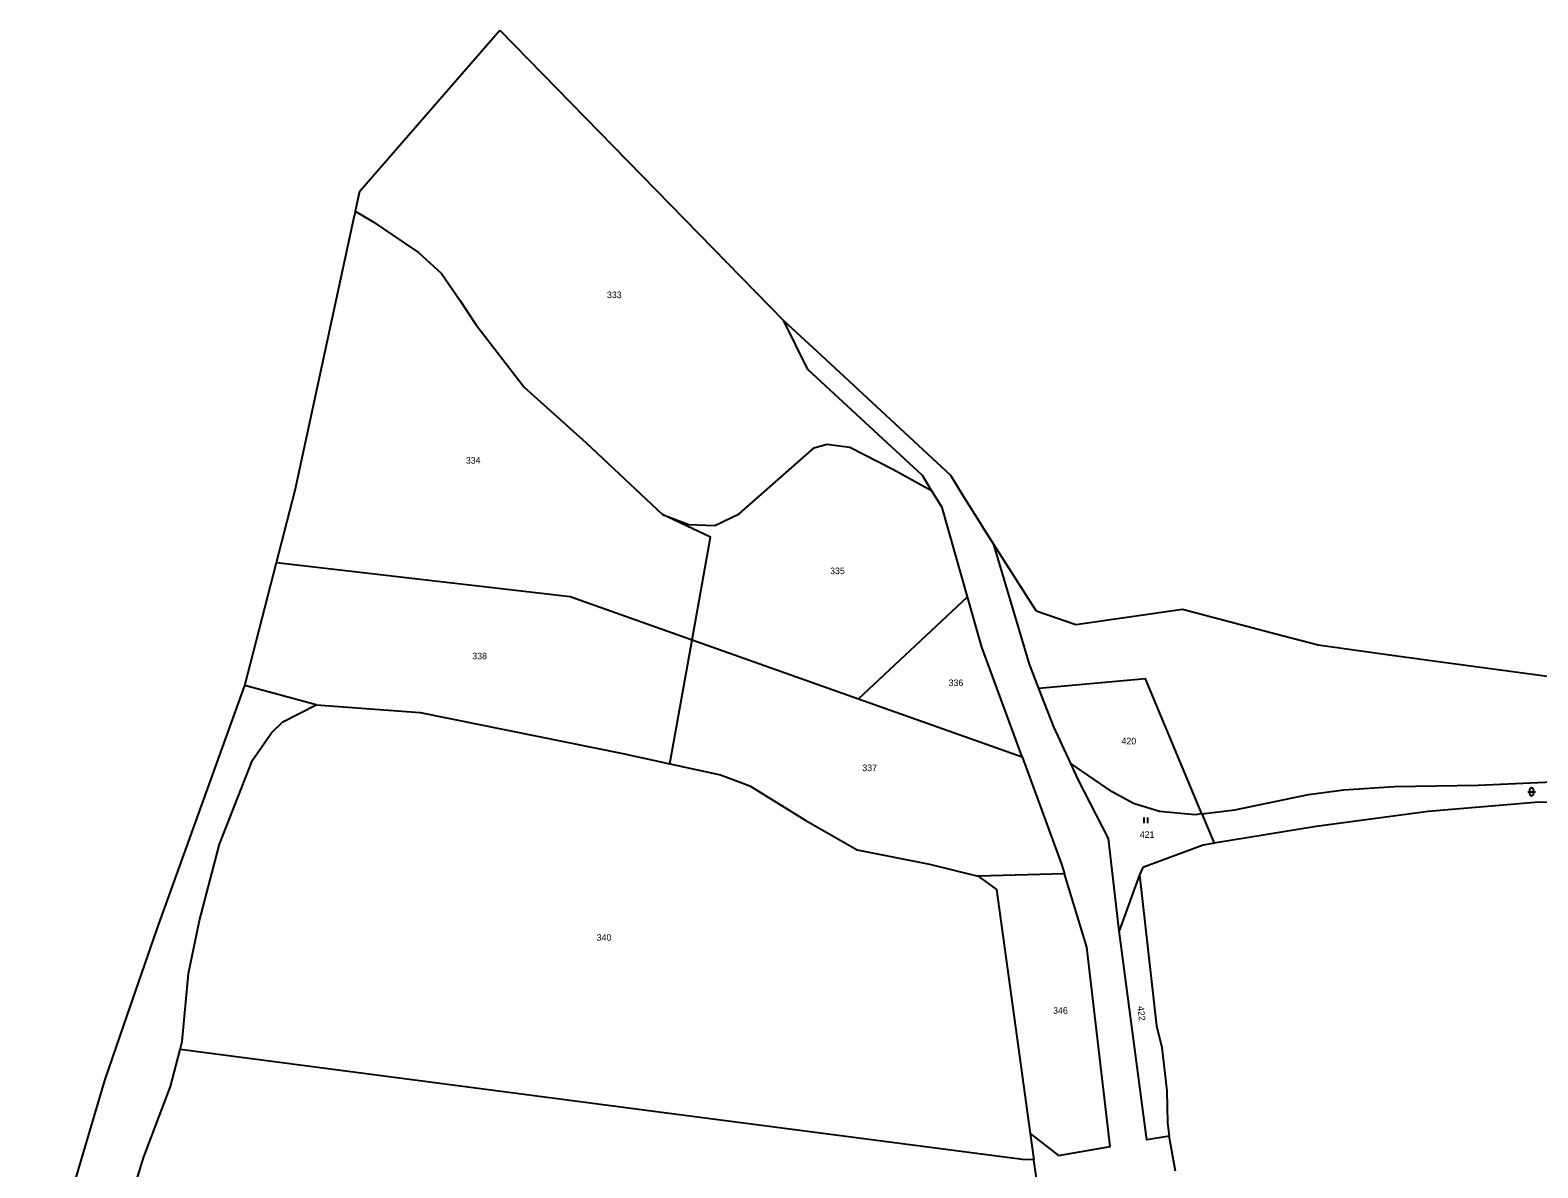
# Model space of a CAD drawing. Extents: x -769392 to -767038, y -1018329 to -1015269.
# Drawn here: x -769066.3 to -768677.2, y -1015766.2 to -1015472.7 of the extents above; entities that cross this region are included whole.
import ezdxf

# ---------------------------------------------------------------- set-up
doc = ezdxf.new("R2010")
doc.units = 0
doc.header["$LTSCALE"] = 0.68
doc.layers.add('1', color=7, linetype='Continuous', lineweight=25)
doc.layers.add('3', color=7, linetype='Continuous', lineweight=25)
doc.layers.add('2', color=7, linetype='Continuous')

msp = doc.modelspace()

# ---------------------------------------------------------------- linework, layer by layer
at = {"layer": '1'}
for p, q in [((-768981.33, -1015514.33), (-768945.15, -1015472.7)), ((-768945.15, -1015472.7), (-768871.81, -1015547.68)), ((-768981.33, -1015514.33), (-768982.42, -1015519.39)), ((-768997.92, -1015591.35), (-768982.65, -1015520.48)), ((-768982.42, -1015519.39), (-768982.65, -1015520.48)), ((-768871.81, -1015547.68), (-768862.21, -1015556.56)), ((-768862.21, -1015556.56), (-768852.61, -1015565.44)), ((-768852.61, -1015565.44), (-768828.82, -1015587.47)), ((-768828.82, -1015587.47), (-768825.84, -1015592.3)), ((-769002.73, -1015610.02), (-768997.92, -1015591.35)), ((-768825.84, -1015592.3), (-768820.65, -1015600.69)), ((-768817.64, -1015605.38), (-768820.65, -1015600.69)), ((-768806.65, -1015622.48), (-768817.64, -1015605.38)), ((-769010.9, -1015641.74), (-769002.73, -1015610.02)), ((-768852.5, -1015645.21), (-768824.37, -1015618.9)), ((-768806.65, -1015622.48), (-768796.44, -1015626.04)), ((-768796.44, -1015626.04), (-768768.87, -1015622.1)), ((-768768.87, -1015622.1), (-768744.81, -1015628.42)), ((-768901.26, -1015661.98), (-768895.5, -1015629.98)), ((-768895.5, -1015629.98), (-768852.5, -1015645.21)), ((-768744.81, -1015628.42), (-768733.91, -1015631.29)), ((-768733.91, -1015631.29), (-768715.44, -1015633.88)), ((-768715.44, -1015633.88), (-768702.2, -1015635.64)), ((-768702.2, -1015635.64), (-768684.96, -1015637.97)), ((-768684.96, -1015637.97), (-768626.24, -1015646.06)), ((-769033.53, -1015704.57), (-769010.9, -1015641.74)), ((-768992.48, -1015646.72), (-769010.9, -1015641.74)), ((-768852.5, -1015645.21), (-768810.3, -1015660.16)), ((-768763.9, -1015674.89), (-768760.74, -1015682.48)), ((-768799.35, -1015690.4), (-768821.66, -1015691)), ((-768780, -1015690.63), (-768785.24, -1015705.08)), ((-769042.15, -1015729.44), (-769033.53, -1015704.57)), ((-769047.08, -1015743.67), (-769042.15, -1015729.44)), ((-769066.34, -1015808.74), (-769047.08, -1015743.67)), ((-768808.19, -1015757.39), (-768807.26, -1015764.14)), ((-768770.74, -1015767.1), (-768772.34, -1015758.02)), ((-768806, -1015773.27), (-768807.26, -1015764.14))]:
    msp.add_line(p, q, dxfattribs=at)
for points in [[(-768982.42, -1015519.39), (-768977.77, -1015522.15), (-768970.03, -1015527.4), (-768966.14, -1015530.1), (-768960.17, -1015535.49), (-768955.46, -1015542.37), (-768951.29, -1015548.66), (-768938.85, -1015564.81), (-768922.86, -1015579.17), (-768903.14, -1015597.65)], [(-768833.66, -1015591.45), (-768836, -1015587.63), (-768865.61, -1015560.23), (-768871.81, -1015547.68)], [(-768903.14, -1015597.65), (-768896.31, -1015600.22), (-768889.6, -1015600.53), (-768883.35, -1015597.51), (-768863.94, -1015580.48), (-768860.71, -1015579.54), (-768854.78, -1015580.31), (-768843.68, -1015585.99), (-768833.66, -1015591.45)], [(-768824.37, -1015618.9), (-768830.95, -1015595.89), (-768833.66, -1015591.45)], [(-768895.5, -1015629.98), (-768890.72, -1015603.48), (-768903.14, -1015597.65)], [(-768805.95, -1015642.53), (-768808.4, -1015636.27), (-768817.64, -1015605.38)], [(-769002.73, -1015610.02), (-768926.96, -1015618.84), (-768895.5, -1015629.98)], [(-768810.3, -1015660.16), (-768820.66, -1015631.9), (-768824.37, -1015618.9)], [(-768763.9, -1015674.89), (-768778.43, -1015640.05), (-768805.95, -1015642.53)], [(-768797.71, -1015661.92), (-768802.09, -1015652.42), (-768805.95, -1015642.53)], [(-769027.63, -1015735.68), (-769027.09, -1015733.58), (-769025.47, -1015716.05), (-769022.64, -1015702.43), (-769017.47, -1015682.73), (-769008.92, -1015661.06), (-769004.07, -1015654.02), (-769001.08, -1015651.11), (-768992.48, -1015646.72)], [(-768992.48, -1015646.72), (-768965.7, -1015648.77), (-768913.4, -1015659.34), (-768901.26, -1015661.98)], [(-768901.26, -1015661.98), (-768888.15, -1015664.84), (-768880.58, -1015667.69), (-768866.09, -1015676.58), (-768852.91, -1015684.2), (-768834.19, -1015687.88), (-768821.66, -1015691)], [(-768810.3, -1015660.16), (-768800.13, -1015687.87), (-768799.35, -1015690.4)], [(-768785.24, -1015705.08), (-768787.98, -1015681.29), (-768795.82, -1015666.01), (-768797.71, -1015661.92)], [(-768763.9, -1015674.89), (-768765.6, -1015675.1), (-768774.84, -1015674.26), (-768781.55, -1015672.2), (-768787.02, -1015669.24), (-768797.71, -1015661.92)], [(-768763.9, -1015674.89), (-768755.4, -1015673.86), (-768736.36, -1015669.92), (-768727.3, -1015668.71), (-768714.2, -1015667.85), (-768692.55, -1015667.47), (-768634.99, -1015664.91), (-768615.15, -1015663.36), (-768593.86, -1015661.93), (-768584.44, -1015662.23), (-768573.84, -1015665.6)], [(-768573.84, -1015665.6), (-768575.17, -1015667.68), (-768589.85, -1015668.08), (-768622.45, -1015669.56), (-768652.26, -1015671.4), (-768677.97, -1015671.97), (-768705.47, -1015674.31), (-768734.39, -1015678.16), (-768760.74, -1015682.48)], [(-768760.74, -1015682.48), (-768763.59, -1015682.95), (-768779.15, -1015688.72), (-768780, -1015690.63)], [(-768821.66, -1015691), (-768816.89, -1015694.42), (-768808.19, -1015757.39)], [(-768808.19, -1015757.39), (-768800.93, -1015763.03), (-768787.6, -1015760.69), (-768793.58, -1015709.3), (-768799.35, -1015690.4)], [(-768780, -1015690.63), (-768775.58, -1015729.62), (-768774.27, -1015735.13), (-768772.94, -1015746.34), (-768772.82, -1015754.57), (-768772.34, -1015758.02)], [(-768772.34, -1015758.02), (-768778.12, -1015759.03), (-768785.24, -1015705.08)], [(-769059, -1015861.06), (-769057.3, -1015844.46), (-769053.28, -1015820.77), (-769048.84, -1015801.56), (-769037, -1015763.4), (-769030.08, -1015745.22), (-769027.63, -1015735.68)], [(-768807.26, -1015764.14), (-768810.2, -1015764.07), (-768908.66, -1015751.21), (-769027.63, -1015735.68)]]:
    msp.add_lwpolyline(points, dxfattribs=at)
at = {"layer": '3'}
for p, q in [((-768679.801, -1015669.191), (-768677.799, -1015669.191)), ((-768679.301, -1015668.691), (-768679.301, -1015669.692)), ((-768678.299, -1015669.692), (-768678.299, -1015668.691)), ((-768778.831, -1015677.3), (-768778.831, -1015675.8)), ((-768777.83, -1015677.3), (-768777.83, -1015675.8))]:
    msp.add_line(p, q, dxfattribs=at)
for centre, start, end in [((-768678.8, -1015668.6909), 0, 180), ((-768678.8, -1015669.6909), 180, 359.98789)]:
    msp.add_arc(centre, 0.5, start, end, dxfattribs=at)

# ---------------------------------------------------------------- texts
at = {"layer": '2'}
for s, p in [('333', (-768917.47, -1015541.835)), ('334', (-768953.88, -1015584.535)), ('335', (-768859.86, -1015613.045)), ('338', (-768952.22, -1015635.015)), ('336', (-768829.27, -1015641.935)), ('420', (-768784.65, -1015656.965)), ('337', (-768851.54, -1015663.865)), ('421', (-768779.93, -1015681.085)), ('340', (-768920.11, -1015707.635)), ('346', (-768802.31, -1015726.465))]:
    msp.add_text(s, height=1.7, dxfattribs=at).set_placement(p)
msp.add_text('422', height=1.7, rotation=277, dxfattribs=at).set_placement((-768780.581, -1015724.591))

doc.saveas('drawing.dxf')
